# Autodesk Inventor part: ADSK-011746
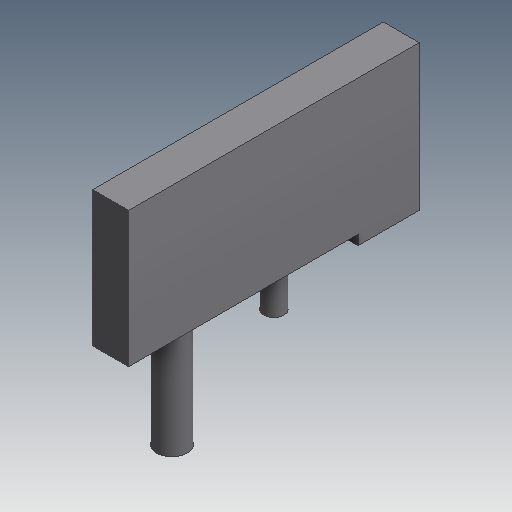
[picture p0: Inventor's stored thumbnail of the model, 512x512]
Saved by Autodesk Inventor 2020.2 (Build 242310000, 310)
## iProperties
Created: 2000-02
Part Number: ADSK-011746
Material: Pearson HRS
Document SubType Name: Modeling
Designer: mpflueger
Density: 7.83 g/cm^3
Appearance: Métal - Acier
Mass: 360.719 g
Surface Area: 120.309 cm^2
Volume: 46.0688 cm^3
Control State: 0
Checked Out: False
Master: False
Shininess: 0.0
Length Units: 11272
Angle Units: 11279
Time Units: 11290
Mass Units: 11286
Length Display Precision: 3
Angle Display Precision: 2
Compacted: True
Dimensions: 3x3,6x0,4 in
Mass: 0,795 lb
VLT_Material: Pearson HRS
Density: 0.0
Volumn: 0.0
Area: 0.0
PropertySet Name: Model Information
Author: mpflueger
Revision Number: -
Title: ADSK-011746
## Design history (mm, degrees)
node "Extrusion1" dims "d2" = 19.05, "d3" = 0
node "Extrusion2" dims "d4" = 71.4375, "d5" = 0
node "Extrusion3" dims "d10" = 12.7, "d11" = 0
node "Extrusion4" dims "d14" = 33.274, "d15" = 0
node "Solide1"
node "Corps solides"
node "Corps surfaciques"
sketch "Sketch1"
  geometry: L1 (0, 0)-(11.176, 0); L2 (11.176, 0)-(11.176, 45.244); L3 (11.176, 45.244)-(0, 45.244); L4 (0, 45.244)-(0, 0)
  constraints: 8 end point, 2 parallel, 1 horizontal, 1 perpendicular
  dimensions: "d0" = 11.176 distance between parallel lines of L4 L2; "d1" = 45.24375 distance between parallel lines of L3 L1
sketch "Sketch2"
  geometry: L1 (11.176, 45.244)-(11.176, 0) reference; L2 (0, 45.244)-(11.176, 45.244); L3 (11.176, 45.244)-(11.176, 3.08); L4 (11.176, 3.08)-(0, 3.08); L5 (0, 3.08)-(0, 45.244); L6 (11.176, 3.08)-(38.1, 3.08) reference
  constraints: 8 end point, 2 parallel, 1 collinear, 1 horizontal, 1 perpendicular, 1 point on line
sketch "Sketch3"
  geometry: L1 (11.176, 0)-(0, 0) reference; L2 (11.176, -71.438)-(11.176, 0) reference; L3 (5.588, 0)-(5.588, -50.8); C1 r 3.175 at (5.588, -50.8)
  constraints: 2 end point, 1 centre point, 1 midpoint, 1 parallel
  dimensions: "d6" = 6.35 diameter of C1; "d9" = 50.8 distance from line of L3.end L1
sketch "Sketch4"
  geometry: L1 (11.176, 0)-(0, 0) reference; L2 (11.176, -71.438)-(11.176, 0) reference; L3 (5.588, 0)-(5.588, -19.05); C1 r 4.762 at (5.588, -19.05)
  constraints: 2 end point, 1 centre point, 1 midpoint, 1 parallel
  dimensions: "d12" = 9.525 diameter of C1; "d13" = 19.05 distance from line of L3.end L1
